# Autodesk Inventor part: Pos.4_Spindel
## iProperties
Created: 2008-10
Part Number: Pos.4_Spindel
Document SubType Name: Modeling
Designer: nkrapf
Density: 1 g/cm^3
Author: nkrapf
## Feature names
1. Umdrehung1 [Revolution]
2. Extrusion1
3. Runde Anordnung1 [Circular Pattern]
4. Extrusion2
5. Fase1 [Chamfer]
6. Bohrung1 [Hole]
